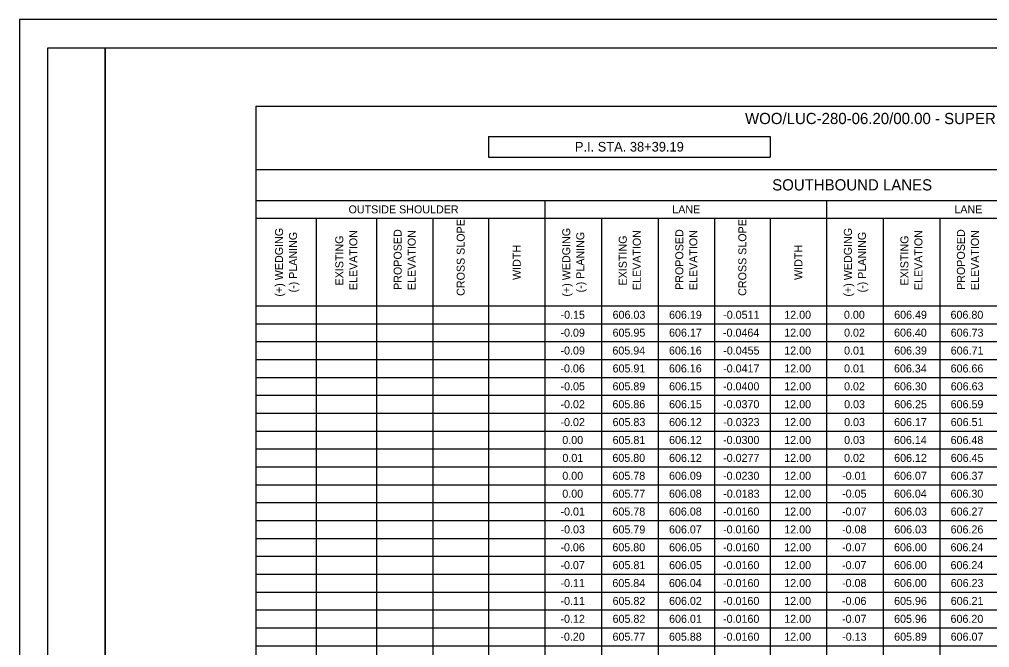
# Model space of a CAD drawing. Extents: x 0 to 34, y 0 to 22.
# Drawn here: x 0 to 16.97, y 11.01 to 22 of the extents above; entities that cross this region are included whole.
import ezdxf

# ---------------------------------------------------------------- set-up
doc = ezdxf.new("R2010")
doc.units = 0
for name, color, linetype in [('Default', 7, 'Continuous'), ('SH_Border', 7, 'Continuous'), ('SH_Cut_Line', 7, 'Continuous')]:
    doc.layers.add(name, color=color, linetype=linetype)

msp = doc.modelspace()

# ---------------------------------------------------------------- linework, layer by layer
at = {"layer": 'Default'}
for p, q in [((4.135, 20.48), (29.368, 20.48)), ((4.135, 20.48), (4.135, 1.522)), ((8.203, 19.953), (13.128, 19.953)), ((8.203, 19.953), (8.203, 19.591)), ((13.128, 19.953), (13.128, 19.591)), ((8.203, 19.591), (13.128, 19.591)), ((4.135, 19.376), (29.368, 19.376)), ((4.135, 18.833), (29.368, 18.833)), ((9.191, 18.833), (9.191, 1.522)), ((14.116, 18.833), (14.116, 1.522)), ((4.135, 18.52), (24.954, 18.52)), ((5.189, 18.52), (5.189, 1.522)), ((6.243, 18.52), (6.243, 1.522)), ((7.231, 18.52), (7.231, 1.522)), ((8.203, 18.52), (8.203, 1.522)), ((10.18, 18.52), (10.18, 1.522)), ((11.168, 18.52), (11.168, 1.522)), ((12.156, 18.52), (12.156, 1.522)), ((13.128, 18.52), (13.128, 1.522)), ((15.104, 18.52), (15.104, 1.522)), ((16.093, 18.52), (16.093, 1.522)), ((4.135, 16.988), (29.368, 16.988)), ((4.135, 16.675), (29.368, 16.675)), ((4.135, 16.362), (29.368, 16.362)), ((4.135, 16.049), (29.368, 16.049)), ((4.135, 15.736), (29.368, 15.736)), ((4.135, 15.424), (29.368, 15.424)), ((4.135, 15.111), (29.368, 15.111)), ((4.135, 14.798), (29.368, 14.798)), ((4.135, 14.485), (29.368, 14.485)), ((4.135, 14.172), (29.368, 14.172)), ((4.135, 13.859), (29.368, 13.859)), ((4.135, 13.546), (29.368, 13.546)), ((4.135, 13.233), (29.368, 13.233)), ((4.135, 12.92), (29.368, 12.92)), ((4.135, 12.607), (29.368, 12.607)), ((4.135, 12.294), (29.368, 12.294)), ((4.135, 11.981), (29.368, 11.981)), ((4.135, 11.668), (29.368, 11.668)), ((4.135, 11.355), (29.368, 11.355)), ((4.135, 11.042), (29.368, 11.042))]:
    msp.add_line(p, q, dxfattribs=at)
at = {"layer": 'SH_Border'}
for points in [[(0.5, 21.5), (1.5, 21.5), (1.5, 0.5), (0.5, 0.5)], [(1.5, 21.5), (33.5, 21.5), (33.5, 0.5), (1.5, 0.5)]]:
    msp.add_lwpolyline(points, close=True, dxfattribs=at)
at = {"layer": 'SH_Cut_Line'}
msp.add_lwpolyline([(0, 0), (34, 0), (34, 22), (0, 22)], close=True, dxfattribs=at)

# ---------------------------------------------------------------- texts
at = {"layer": 'Default'}
for s, height, p in [('WOO/LUC-280-06.20/00.00 - SUPERELEVATION TABLE', 0.196, (12.689, 20.168)), ('P.I. STA. 38+39.19', 0.168, (9.714, 19.688)), ('SOUTHBOUND LANES', 0.196, (13.164, 19.007)), ('OUTSIDE SHOULDER', 0.14, (5.756, 18.606)), ('LANE', 0.14, (11.417, 18.606)), ('LANE', 0.14, (16.35, 18.606)), ('-0.15', 0.14, (9.463, 16.762)), ('606.03', 0.14, (10.373, 16.762)), ('606.19', 0.14, (11.36, 16.762)), ('-0.0511', 0.14, (12.307, 16.762)), ('12.00', 0.14, (13.375, 16.762)), ('0.00', 0.14, (14.419, 16.762)), ('606.49', 0.14, (15.297, 16.762)), ('606.80', 0.14, (16.283, 16.762)), ('-0.09', 0.14, (9.462, 16.449)), ('605.95', 0.14, (10.373, 16.449)), ('606.17', 0.14, (11.36, 16.449)), ('-0.0464', 0.14, (12.304, 16.449)), ('12.00', 0.14, (13.375, 16.449)), ('0.02', 0.14, (14.421, 16.449)), ('606.40', 0.14, (15.295, 16.449)), ('606.73', 0.14, (16.286, 16.449)), ('-0.09', 0.14, (9.462, 16.136)), ('605.94', 0.14, (10.37, 16.136)), ('606.16', 0.14, (11.359, 16.136)), ('-0.0455', 0.14, (12.308, 16.136)), ('12.00', 0.14, (13.375, 16.136)), ('0.01', 0.14, (14.421, 16.136)), ('606.39', 0.14, (15.297, 16.136)), ('606.71', 0.14, (16.286, 16.136)), ('-0.06', 0.14, (9.461, 15.823)), ('605.91', 0.14, (10.373, 15.823)), ('606.16', 0.14, (11.359, 15.823)), ('-0.0417', 0.14, (12.306, 15.823)), ('12.00', 0.14, (13.375, 15.823)), ('0.01', 0.14, (14.421, 15.823)), ('606.34', 0.14, (15.294, 15.823)), ('606.66', 0.14, (16.284, 15.823)), ('-0.05', 0.14, (9.463, 15.51)), ('605.89', 0.14, (10.372, 15.51)), ('606.15', 0.14, (11.361, 15.51)), ('-0.0400', 0.14, (12.305, 15.51)), ('12.00', 0.14, (13.375, 15.51)), ('0.02', 0.14, (14.421, 15.51)), ('606.30', 0.14, (15.295, 15.51)), ('606.63', 0.14, (16.286, 15.51)), ('-0.02', 0.14, (9.462, 15.197)), ('605.86', 0.14, (10.371, 15.197)), ('606.15', 0.14, (11.361, 15.197)), ('-0.0370', 0.14, (12.305, 15.197)), ('12.00', 0.14, (13.375, 15.197)), ('0.03', 0.14, (14.422, 15.197)), ('606.25', 0.14, (15.298, 15.197)), ('606.59', 0.14, (16.285, 15.197)), ('-0.02', 0.14, (9.462, 14.884)), ('605.83', 0.14, (10.373, 14.884)), ('606.12', 0.14, (11.361, 14.884)), ('-0.0323', 0.14, (12.308, 14.884)), ('12.00', 0.14, (13.375, 14.884)), ('0.03', 0.14, (14.422, 14.884)), ('606.17', 0.14, (15.296, 14.884)), ('606.51', 0.14, (16.286, 14.884)), ('0.00', 0.14, (9.494, 14.571)), ('605.81', 0.14, (10.373, 14.571)), ('606.12', 0.14, (11.361, 14.571)), ('-0.0300', 0.14, (12.305, 14.571)), ('12.00', 0.14, (13.375, 14.571)), ('0.03', 0.14, (14.422, 14.571)), ('606.14', 0.14, (15.294, 14.571)), ('606.48', 0.14, (16.284, 14.571)), ('0.01', 0.14, (9.496, 14.258)), ('605.80', 0.14, (10.37, 14.258)), ('606.12', 0.14, (11.361, 14.258)), ('-0.0277', 0.14, (12.306, 14.258)), ('12.00', 0.14, (13.375, 14.258)), ('0.02', 0.14, (14.421, 14.258)), ('606.12', 0.14, (15.297, 14.258)), ('606.45', 0.14, (16.286, 14.258)), ('0.00', 0.14, (9.494, 13.945)), ('605.78', 0.14, (10.371, 13.945)), ('606.09', 0.14, (11.36, 13.945)), ('-0.0230', 0.14, (12.305, 13.945)), ('12.00', 0.14, (13.375, 13.945)), ('-0.01', 0.14, (14.387, 13.945)), ('606.07', 0.14, (15.296, 13.945)), ('606.37', 0.14, (16.285, 13.945)), ('0.00', 0.14, (9.494, 13.632)), ('605.77', 0.14, (10.372, 13.632)), ('606.08', 0.14, (11.359, 13.632)), ('-0.0183', 0.14, (12.308, 13.632)), ('12.00', 0.14, (13.375, 13.632)), ('-0.05', 0.14, (14.387, 13.632)), ('606.04', 0.14, (15.294, 13.632)), ('606.30', 0.14, (16.283, 13.632)), ('-0.01', 0.14, (9.462, 13.319)), ('605.78', 0.14, (10.371, 13.319)), ('606.08', 0.14, (11.359, 13.319)), ('-0.0160', 0.14, (12.305, 13.319)), ('12.00', 0.14, (13.375, 13.319)), ('-0.07', 0.14, (14.386, 13.319)), ('606.03', 0.14, (15.298, 13.319)), ('606.27', 0.14, (16.285, 13.319)), ('-0.03', 0.14, (9.463, 13.006)), ('605.79', 0.14, (10.372, 13.006)), ('606.07', 0.14, (11.36, 13.006)), ('-0.0160', 0.14, (12.305, 13.006)), ('12.00', 0.14, (13.375, 13.006)), ('-0.08', 0.14, (14.386, 13.006)), ('606.03', 0.14, (15.298, 13.006)), ('606.26', 0.14, (16.284, 13.006)), ('-0.06', 0.14, (9.461, 12.694)), ('605.80', 0.14, (10.37, 12.694)), ('606.05', 0.14, (11.361, 12.694)), ('-0.0160', 0.14, (12.305, 12.694)), ('12.00', 0.14, (13.375, 12.694)), ('-0.07', 0.14, (14.386, 12.694)), ('606.00', 0.14, (15.295, 12.694)), ('606.24', 0.14, (16.283, 12.694)), ('-0.07', 0.14, (9.461, 12.381)), ('605.81', 0.14, (10.373, 12.381)), ('606.05', 0.14, (11.361, 12.381)), ('-0.0160', 0.14, (12.305, 12.381)), ('12.00', 0.14, (13.375, 12.381)), ('-0.07', 0.14, (14.386, 12.381)), ('606.00', 0.14, (15.295, 12.381)), ('606.24', 0.14, (16.283, 12.381)), ('-0.11', 0.14, (9.462, 12.068)), ('605.84', 0.14, (10.37, 12.068)), ('606.04', 0.14, (11.358, 12.068)), ('-0.0160', 0.14, (12.305, 12.068)), ('12.00', 0.14, (13.375, 12.068)), ('-0.08', 0.14, (14.386, 12.068)), ('606.00', 0.14, (15.295, 12.068)), ('606.23', 0.14, (16.286, 12.068)), ('-0.11', 0.14, (9.462, 11.755)), ('605.82', 0.14, (10.373, 11.755)), ('606.02', 0.14, (11.361, 11.755)), ('-0.0160', 0.14, (12.305, 11.755)), ('12.00', 0.14, (13.375, 11.755)), ('-0.06', 0.14, (14.385, 11.755)), ('605.96', 0.14, (15.296, 11.755)), ('606.21', 0.14, (16.286, 11.755)), ('-0.12', 0.14, (9.462, 11.442)), ('605.82', 0.14, (10.373, 11.442)), ('606.01', 0.14, (11.361, 11.442)), ('-0.0160', 0.14, (12.305, 11.442)), ('12.00', 0.14, (13.375, 11.442)), ('-0.07', 0.14, (14.386, 11.442)), ('605.96', 0.14, (15.296, 11.442)), ('606.20', 0.14, (16.283, 11.442)), ('-0.20', 0.14, (9.46, 11.129)), ('605.77', 0.14, (10.372, 11.129)), ('605.88', 0.14, (11.359, 11.129)), ('-0.0160', 0.14, (12.305, 11.129)), ('12.00', 0.14, (13.375, 11.129)), ('-0.13', 0.14, (14.388, 11.129)), ('605.89', 0.14, (15.297, 11.129)), ('606.07', 0.14, (16.285, 11.129))]:
    msp.add_text(s, height=height, dxfattribs=at).set_placement(p)
for s, p in [('CROSS SLOPE', (7.787, 17.163)), ('CROSS SLOPE', (12.712, 17.163)), ('(+) WEDGING', (4.61, 17.15)), ('(+) WEDGING', (9.633, 17.15)), ('(+) WEDGING', (14.558, 17.15)), ('(-) PLANING', (4.855, 17.222)), ('EXISTING ', (5.664, 17.345)), ('ELEVATION', (5.909, 17.263)), ('PROPOSED ', (6.685, 17.267)), ('ELEVATION', (6.93, 17.263)), ('(-) PLANING', (9.878, 17.222)), ('EXISTING ', (10.621, 17.345)), ('ELEVATION', (10.866, 17.263)), ('PROPOSED ', (11.61, 17.267)), ('ELEVATION', (11.855, 17.263)), ('(-) PLANING', (14.803, 17.222)), ('EXISTING ', (15.546, 17.345)), ('ELEVATION', (15.791, 17.263)), ('PROPOSED ', (16.534, 17.267)), ('ELEVATION', (16.779, 17.263)), ('WIDTH', (8.767, 17.441)), ('WIDTH', (13.692, 17.441))]:
    msp.add_text(s, height=0.14, rotation=90, dxfattribs=at).set_placement(p)

doc.saveas('drawing.dxf')
